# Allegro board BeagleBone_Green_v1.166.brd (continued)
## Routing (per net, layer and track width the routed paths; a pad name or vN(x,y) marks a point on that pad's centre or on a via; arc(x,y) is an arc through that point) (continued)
DDR_DQS0: length 23.3
  TOP w0.095: U5.P1 54.02,98.04 55.15,98.04 56.02,98.91 64.39,98.91 64.52,98.78 64.52,98.56 64.39,98.43 63.4,98.43 63.09,98.11 63.09,97.4 64.62,95.87 64.62,91.66 64.33,91.37 64.15,91.37 64.07,91.45 64.07,91.85 64,91.93 63.77,91.93 63.69,91.85 63.69,91.57 63.61,91.49 63.02,91.49 62.94,91.57 62.94,91.81 63.02,91.89 U12.F3
DDR_DQS1: length 20.3
  TOP w0.095: v1(55.24,95.94) 54.84,95.54 U5.L1
  TOP w0.121: v1(66.9,94.69) U12.C7
  BOTTOM w0.095: v1(55.24,95.94) 55.02,96.16 55.02,96.37 55.14,96.49 55.87,96.49 56.16,96.79 56.16,97.17 55.78,97.55 55.78,97.78 56.15,98.15 64.26,98.15 65.53,96.88 65.53,96.49 65.3,96.27 65.04,96.27 64.74,95.98 64.74,95.39 65.04,95.1 66.94,95.1 67.01,95.02 67.01,94.77 66.94,94.69 v1(66.9,94.69)
DDR_DQSN0: length 23.3
  TOP w0.095: U12.G3 64.45,91.09 64.9,91.54 64.9,95.99 63.37,97.52 63.37,98 63.52,98.15 64.5,98.15 64.8,98.44 64.8,98.9 64.5,99.19 55.91,99.19 55.04,98.32 53.5,98.32 U5.P2
DDR_DQSN1: length 20.3
  TOP w0.095: v1(54.48,95.94) 53.52,95.94 U5.L2
  TOP w0.121: v1(66.9,95.49) U12.B7
  BOTTOM w0.095: v1(66.9,95.49) 66.78,95.38 65.15,95.38 65.02,95.5 65.02,95.86 65.15,95.99 65.42,95.99 65.81,96.38 65.81,96.99 64.37,98.43 56.04,98.43 55.5,97.89 55.5,97.43 55.88,97.05 55.88,96.9 55.75,96.77 55.03,96.77 54.74,96.48 54.74,96.19 v1(54.48,95.94)
DDR_ODT: length 24.1
  TOP w0.121: U5.G1 55.08,92.34 55.72,92.34 56.52,91.54 56.52,90.65 56.9,90.27 57.53,90.27 57.78,90.02 57.78,86.82 57.89,86.72 58.04,86.72 58.15,86.82 58.15,89.38 58.26,89.49 58.69,89.49 58.8,89.38 58.8,88.75 58.95,88.6 58.95,87.22 59.07,87.1 59.31,87.1 59.44,87.22 59.44,88.87 v1(59.31,89) ; v1(61.3,88.29) U12.K1
  LYR3 w0.133: v1(61.3,88.29) 60.63,88.29 60.32,87.99 59.44,87.99 59.31,88.11 59.31,88.37 59.44,88.49 59.69,88.49 59.82,88.62 59.82,90.02 59.56,90.27 59.18,90.27 59.05,90.14 59.05,89.76 59.31,89.51 v1(59.31,89)
DDR_RASN: length 24
  TOP w0.121: v1(62.9,89.09) U12.J3 ; U5.G4 v1(51.92,91.94)
  LYR3 w0.121: 52.73,89.89 52.57,89.89 52.32,90.14 52.32,90.53 52.11,90.74 51.73,90.74 51.52,90.95 51.52,91.54 v1(51.92,91.94)
  LYR3 w0.133: 52.73,89.89 55.63,89.89 56.13,90.4 56.13,91.03 55.64,91.53 54.86,91.53 54.74,91.66 54.74,92.56 54.86,92.68 56.39,92.68 57.89,91.18 59.16,91.18 60.82,89.52 62.75,89.52 62.99,89.76 63.5,89.76 64.24,89.03 64.24,88.85 64.09,88.7 63.91,88.7 63.52,89.09 v1(62.9,89.09)
DDR_RESETN: length 20.7
  TOP w0.121: U5.G2 53.52,92.74 55.83,92.74 56.9,91.67 56.9,90.91 57.15,90.65 57.78,90.65 58.15,90.29 59.29,90.29 59.82,89.76 59.82,87.1 60.07,86.84 60.07,83.16 60.2,83.03 61.64,83.03 v1(62.1,83.49) U12.T2
  BOTTOM w0.121: v1(62.1,83.49) U12.T2 63.35,83.89 63.75,84.29 R97.2
DDR_VREF: length 27.1
  TOP w0.305: v1(51.92,93.54) U5.J4 ; v1(61.3,90.69) U12.H1 ; v1(67.7,86.69) U12.M8
  BOTTOM w0.381: v1(67.7,86.69) 66.57,86.69 66.17,87.09 C124.1 R100.1 65.41,88.51 65.02,88.89 64.86,88.89 64.85,88.89 64.62,88.89 64.39,89.13 C123.1 R98.2 ; v1(51.92,93.54) 52.46,94.08 55.88,94.08 56.43,93.54 C28.1 56.77,92.56 57.71,91.62 60.76,91.62 60.87,91.73 61.73,91.73 61.74,91.72 63.91,91.72 64.39,91.24 R98.2 ; R98.2 63.79,90.69 63.22,90.12 61.87,90.12 v1(61.3,90.69)
DDR_VTP: length 6.7
  TOP w0.305: v1(52.72,93.54) U5.J3
  BOTTOM w0.381: R22.2 56.26,91.29 56.26,92.81 55.54,93.54 v1(52.72,93.54)
DDR_WEN: length 23.9
  TOP w0.121: v1(62.9,87.49) U12.L3 ; v1(56.77,82.65) 56.77,82.8 54.86,84.71 54.86,85.45 54.36,85.95 53.64,85.95 53.51,86.08 53.51,87.7 53.12,88.1 U5.B2
  LYR3 w0.133: v1(56.77,82.65) 56.78,82.65 57.03,82.65 58.17,81.51 63.63,81.51 64.52,82.4 64.52,85.7 64.9,86.08 64.9,86.84 63.88,87.86 63.27,87.86 v1(62.9,87.49)
EHRPWM1A: length 42.1
  TOP w0.121: v1(41.73,103.43) 42.42,104.11 43.03,104.11 43.92,103.23 43.92,100.74 U5.U14
  LYR4 w0.133: P9.14 36.3,69.6 36.3,74.24 36.96,74.9 36.96,84.05 36.82,84.18 36.82,88.24 36.95,88.37 36.95,90.91 37.46,91.41 37.46,92.19 38.63,93.37 38.63,98.68 41.73,101.78 v1(41.73,103.43)
EHRPWM1B: length 36.3
  TOP w0.121: v1(43.12,99.94) U5.T14
  LYR4 w0.133: v1(43.12,99.94) 43.12,100.49 42.48,101.12 42.04,101.12 39.37,98.45 39.37,92.3 37.69,90.63 37.69,88.01 37.88,87.82 37.88,84.52 38.35,84.05 38.35,70.08 P9.16
EHRPWM2A: length 16.8
  TOP w0.121: P8.19 45.97,113.26 45.97,110.59 47.57,108.99 47.57,101.75 47.36,101.53 47.35,101.53 47.12,101.3 47.12,101.2 47.12,101.19 47.12,100.74 U5.U10
EHRPWM2B: length 28.2
  TOP w0.121: v1(46.32,99.94) U5.T10
  LYR3 w0.133: P8.13 34.9,113.87 34.9,108.8 35.85,107.85 38.66,107.85 40,109.19 43.69,109.19 44.7,108.18 44.7,106.78 44.1,106.18 44.1,105.67 44.98,104.78 44.98,104.47 45.78,103.68 45.78,100.48 v1(46.32,99.94)
EMMC_RSTN: length 4.8
  TOP w0.203: U13.K5 v1(30.49,108.79)
  BOTTOM w0.121: R162.2 R111.2 30.61,109.69 30.49,109.58 v1(30.49,108.79)
EMMC_VCCI: length 2.5
  TOP w0.076: 33.27,110.47 33.24,110.45 33.24,110.03 U13.C2
  TOP w0.121: 33.27,110.47 33.74,110.95 v1(34.01,110.95)
  BOTTOM w0.121: v1(34.01,110.95) 34.01,111.02 33.78,111.25 C125.1
ENZ_KALDO_1P8V: length 3.4
  TOP w0.121: U5.B4 v1(51.92,87.93)
  BOTTOM w0.121: v1(51.92,87.93) 52.51,87.34 R54.2
ETH_TXD4: length 4.4
  TOP w0.121: v1(30.61,99.73) 28.13,99.73 27.73,99.33 U14.18
  BOTTOM w0.121: R145.1 v1(30.61,99.73)
GPIO0_7: length 45.9
  TOP w0.121: R50.1 37.72,83.41 v1(37.46,83.16)
  BOTTOM w0.121: P9.42 70.29,71.16 68.85,71.16 61.29,78.71 48.39,78.71 48.2,78.53 44.15,78.53 42.67,80.01 42.67,83.03 42.04,83.67 R51.1 41.15,84.3 40.77,84.68 39.24,84.68 38.61,85.32 38.1,85.32 37.86,85.08 37.86,84.58 37.46,84.18 v1(37.46,83.16)
GPIO0_7SRC: length 9.2
  TOP w0.121: R50.2 37.46,82.4 37.01,82.85 37.01,85.12 38.48,86.59 38.48,87.6 40.01,89.14 U5.C18
GPIO0_26: length 30.5
  TOP w0.121: v1(45.52,99.94) U5.T11
  LYR3 w0.133: v1(45.52,99.94) 45.52,103.56 44.63,104.44 44.63,104.81 43.81,105.63 43.81,106.39 44.45,107.04 44.45,108.05 43.69,108.81 39.96,108.81 38.76,107.61 35.75,107.61 34.66,108.7 34.66,108.9 34.66,114.82 35.05,115.21 35.05,116.56 P8.14
GPIO0_27: length 18.3
  TOP w0.121: P8.17 41.4,114.91 41.86,114.45 42.93,114.45 43.23,114.15 44.07,114.15 44.7,113.51 44.7,110.5 45.59,109.61 45.59,105.51 45.12,105.04 45.12,102.24 45.51,101.84 45.51,100.73 U5.U12
GPIO1_12: length 30.2
  TOP w0.121: v1(44.72,99.94) U5.T12
  LYR3 w0.133: v1(44.72,99.94) 44.72,103.26 43.89,104.09 43.89,104.88 43.28,105.49 43.28,107.57 42.55,108.31 40.29,108.31 39.12,107.13 35.55,107.13 35.37,106.95 34.84,106.95 33.66,108.14 33.66,108.84 32.83,109.67 32.83,116.87 P8.12
GPIO1_13: length 28.5
  TOP w0.121: v1(44.72,99.14) U5.R12
  LYR3 w0.121: 45.16,103.4 45.16,100.15 45.12,100.1 45.12,99.77 45.16,99.73 45.16,99.58 v1(44.72,99.14)
  LYR3 w0.133: P8.11 33.38,114.88 33.38,109.63 34.09,108.92 34.09,108.04 34.93,107.19 35.27,107.19 35.45,107.37 38.94,107.37 40.13,108.56 42.67,108.56 43.56,107.67 43.56,105.54 44.37,104.73 44.37,104.19 45.16,103.4
GPIO1_14: length 22.1
  TOP w0.121: P8.16 37.85,116.81 37.85,114.6 39.19,113.26 42.42,113.26 43.18,112.5 43.18,110.46 44.45,109.19 44.45,107.04 43.94,106.53 43.94,104.11 44.32,103.74 44.32,101.48 U5.V13
GPIO1_15: length 19.9
  TOP w0.121: U5.U13 44.72,100.74 44.72,100.9 44.72,101.69 44.58,101.83 44.58,103.86 44.2,104.24 44.2,106.27 44.83,106.91 44.83,109.32 43.43,110.72 43.43,112.75 42.55,113.63 39.43,113.63 38.86,114.2 P8.15
GPIO1_16: length 55
  LYR4 w0.133: v1(43.69,108.18) 43.43,108.43 40.64,108.43 37.59,105.38 37.59,104.88 34.92,102.21 34.92,89.2 32.64,86.92 32.64,84.58 33.15,84.07 33.15,72.49 32.64,71.98 32.64,69.19 33.66,68.17 37.72,68.17 P9.15
  BOTTOM w0.133: v1(43.69,108.18) 43.81,108.05 R160.2 R161.2
GPIO1_17: length 53.4
  TOP w0.121: v1(42.8,103.71) 42.85,103.71 43.52,103.04 U5.V14
  LYR4 w0.133: v1(42.8,103.71) 42.76,103.71 42.09,103.04 42.09,101.68 39.1,98.69 39.1,93.5 37.69,92.1 37.69,91.29 37.21,90.8 37.21,88.24 37.06,88.09 37.06,84.43 37.87,83.62 37.87,75.11 36.7,73.94 v1(36.7,71.6)
  BOTTOM w0.121: P9.23 47.75,68.3 47.75,69.95 46.99,70.71 37.59,70.71 v1(36.7,71.6)
GPIO1_28: length 38.6
  TOP w0.121: v1(38.4,102.46) 38.41,102.46 38.97,101.9 38.97,101.46 39.16,101.27 39.16,101.23 40.05,100.34 U5.U18
  LYR4 w0.133: v1(38.4,102.46) 38.35,102.46 37.92,102.03 37.92,101.75 37.71,101.54 36.54,101.54 35.69,100.69 35.69,88.62 35.43,88.37 35.43,82.91 34.06,81.53 34.06,70.99 33.78,70.71 P9.12
GPIO1_29: length 18
  TOP w0.121: P8.26 50.55,116.81 50.55,114.53 50.8,114.27 50.8,110.21 49.4,108.81 49.4,104.37 49.92,103.85 U5.V6
GPIO2_1: length 20.3
  TOP w0.121: P8.18 40.41,116.84 40.41,114.81 41.15,114.07 42.62,114.07 44.45,112.24 44.45,110.21 45.34,109.32 45.34,105.64 44.83,105.13 44.83,102.08 45.12,101.8 U5.V12
GPIO3_18: length 5.9
  TOP w0.121: v1(41.4,85.32) 42.16,85.32 43.49,86.64 44,86.64 44.71,87.36 44.71,87.93 U5.B12
  BOTTOM w0.121: v1(41.4,85.32) R51.2
GPIO3_19: length 28.2
  TOP w0.121: v1(43.92,88.73) U5.C13
  LYR4 w0.133: v1(43.92,88.73) 43.25,88.07 43.25,86.8 43.78,86.27 43.78,82.49 44.32,81.94 44.32,79.12 46.58,76.86 46.58,75.51 47.88,74.22 47.88,72.34 50.16,70.05 50.16,68.94 50.93,68.17 52.96,68.17 P9.27
GPIO3_20: length 5.9
  TOP w0.121: U5.D13 v1(43.92,90.34)
  BOTTOM w0.121: v1(43.92,90.34) 43.52,89.94 43.52,86.51 43.94,86.08 R20.2
GPIO3_21: length 58.4
  TOP w0.121: v1(39.95,106.53) 39.75,106.53 39.37,106.91 ; U5.A14 43.52,87.34 42.13,85.95 41.15,85.95 v1(40.51,85.32) 40.39,85.19 40.39,81.76 41.78,80.37 41.78,76.35 42.65,75.49 42.65,72.01 43.18,71.48 45.59,71.48 46.33,70.74 49.63,70.74 50.29,70.08 50.29,68.3 P9.25
  LYR3 w0.133: v1(40.51,85.32) 40.13,85.32 39.37,86.08 37.08,86.08 36.45,86.72 v1(36.45,88.67)
  LYR4 w0.133: v1(36.45,88.67) 36.45,99.29 36.7,99.54 38.73,99.54 40.13,100.94 40.13,101.45 39.88,101.7 39.88,106.46 v1(39.95,106.53)
GRN_C: length 2
  BOTTOM w0.381: P5.10 6.27,97.71 6.6,97.38 R132.2
GRNA: length 30
  TOP w0.121: 25.73,92.93 v1(25.84,92.81)
  TOP w0.254: U14.3 25.73,92.93
  BOTTOM w0.254: v1(25.84,92.81) 25.59,93.07 25.02,93.07 24.77,92.82 24.77,92.69 24.51,92.43 22.35,92.43 19.18,89.26 16.51,89.26 13.59,92.18 12.19,92.18 11.56,92.81 11.56,93.19 9.02,95.73 C165.1 C163.1 9.02,97 7.49,98.53 7.49,98.84 7.23,99.24 6.16,100.3 5.74,100.3 P5.9
HDMI_INT: length 22.1
  TOP w0.121: U5.U16 41.52,100.73 41.52,101.96 41.1,102.39 39.09,102.39 38.51,102.97 37.78,102.97 37.76,102.99 37.43,102.99 37.41,102.97 36.22,102.97 35.94,102.69 27.28,102.69 26.14,103.84 R170.1 23.37,103.86 R169.1
HDMICLK_DISN: length 5.3
  TOP w0.121: v1(40.89,104.62) 40.89,104.75 41.14,105 41.16,105 41.74,105.58 Y4.1 ; U5.V17 41.12,101.76 v1(41.05,101.83)
  LYR3 w0.133: v1(40.89,104.62) 40.89,101.98 v1(41.05,101.83)
I2C0_SCL: length 27.9
  TOP w0.121: R3.2 27.43,85.57 v1(28.32,84.68) ; v1(28.32,79.16) 28.11,79.37 U2.28 ; v1(41.52,88.73) U5.C16
  LYR4 w0.133: v1(28.32,84.68) 28.96,84.05 28.96,79.79 v1(28.32,79.16)
  BOTTOM w0.121: v1(28.32,84.68) 29.59,84.68 30.38,85.47 30.38,86.87 31.5,87.99 U7.1 33.12,87.99 33.38,87.73 37.57,87.73 39.07,86.23 40.53,86.23 41.12,86.81 41.12,88.34 v1(41.52,88.73)
I2C0_SDA: length 33.2
  TOP w0.121: U2.27 27.88,78.97 v1(28.32,78.52) ; U5.C17 40.72,88.74 40.12,88.74 38.73,87.35 38.73,86.54 38.73,86.53 38.73,86.49 37.46,85.22 v1(37.46,84.81) ; R4.2 v1(28.38,85.7)
  LYR3 w0.133: v1(37.46,84.81) 36.2,84.81 34.67,86.33 29.02,86.33 v1(28.38,85.7)
  LYR4 w0.133: v1(28.32,78.52) 29.21,79.41 29.21,84.87 v1(28.38,85.7)
  BOTTOM w0.121: v1(28.38,85.7) 27.81,85.13 27.81,84.43 28.07,84.18 29.72,84.18 30.73,85.19 31.88,85.19 32.22,85.53 U7.3
I2C1_SCL: length 25.2
  TOP w0.121: U5.A16 v1(41.52,87.13)
  TOP w0.133: P9.17 42.55,68.17 42.55,70.71 41.4,71.86 v1(41.4,72.11)
  LYR4 w0.133: v1(41.4,72.11) 44.7,75.41 44.87,75.41 45.65,76.19 45.65,76.8 43.27,79.18 43.27,79.98 42.63,80.62 42.63,85.87 41.52,86.98 v1(41.52,87.13)
I2C1_SDA: length 23.1
  TOP w0.121: U5.B16 v1(41.52,87.93)
  LYR4 w0.133: P9.18 41,69.98 41,72.28 44.38,75.67 44.8,75.67 45.41,76.29 45.41,76.7 43.03,79.08 43.03,79.88 42.39,80.52 42.39,85.67 41.11,86.95 41.11,87.53 v1(41.52,87.93)
I2C2_SCL: length 73.5
  TOP w0.121: U5.D17 40.72,89.54 39.9,89.54 38.86,88.49 v1(38.1,88.49) ; J4.1 v1(75.77,86.67)
  LYR3 w0.133: v1(41.12,78.71) 45.82,78.71 49,75.54 54.71,75.54 57.66,78.49 69.69,78.49 75.18,83.98 75.18,86.08 v1(75.77,86.67)
  LYR4 w0.133: P9.19 42.8,68.17 40.82,68.17 40.02,68.97 40.02,77.62 v1(41.12,78.71) 38.86,80.98 38.86,85.47 38.5,85.83 38.5,88.09 v1(38.1,88.49)
I2C2_SDA: length 71.1
  TOP w0.121: U5.D18 39.8,89.94 38.86,89 38.23,89 v1(38.1,89.13) ; J4.2 v1(75.69,84.67)
  LYR3 w0.133: v1(41.27,77.95) 41.53,78.21 45.92,78.21 48.83,75.3 54.88,75.3 57.78,78.21 69.74,78.21 75.69,84.16 v1(75.69,84.67)
  LYR4 w0.133: v1(38.1,89.13) 38.73,88.49 38.73,86.06 39.14,85.65 39.14,81.14 41.06,79.22 41.19,79.22 41.55,78.86 41.55,78.22 v1(41.27,77.95) 40.26,76.94 40.26,69.06 40.77,68.55 42.93,68.55 P9.20
JTAG_EMU0: length 23.6
  TOP w0.121: R23.2 37.45,77 35.69,78.77 v1(35.69,80.05) ; v1(43.12,88.73) U5.C14
  LYR3 w0.133: v1(35.69,80.05) 36.26,80.62 39.75,80.62 40,80.87 v1(43.81,80.87)
  LYR4 w0.133: v1(43.12,88.73) 43.12,88.36 42.99,88.24 42.99,86.68 43.36,86.31 43.36,86.24 43.37,86.22 43.37,81.32 v1(43.81,80.87)
  BOTTOM w0.121: P2.13 v1(35.69,80.05)
JTAG_EMU1: length 15.3
  TOP w0.121: R24.2 37.66,80.24 v1(37.46,80.05) ; v1(41.12,80.37) 41.05,80.37 39.99,81.43 39.99,85.43 40.89,86.33 42.16,86.33 43.12,87.29 43.12,87.94 U5.B14
  BOTTOM w0.121: v1(41.12,80.37) 40.89,80.37 40.58,80.05 P2.14 v1(37.46,80.05)
JTAG_TCK: length 24.1
  TOP w0.121: v1(42.55,77.06) 42.29,77.32 42.29,80.49 41.78,81 41.78,84.43 43.75,86.39 44.13,86.39 44.8,87.07 44.8,87.07 45.12,87.38 U5.A12
  LYR3 w0.133: v1(35.69,77.51) 42.1,77.51 v1(42.55,77.06)
  BOTTOM w0.121: P2.11 35.5,78.78 35.69,78.59 v1(35.69,77.51) P2.9
JTAG_TDI: length 24.1
  TOP w0.121: v1(43.19,77.03) 42.67,77.55 42.67,80.71 42.2,81.19 42.2,84.34 43.91,86.05 44.27,86.05 45.52,87.29 45.52,87.94 U5.B11
  BOTTOM w0.121: v1(43.19,77.03) 42.81,76.65 41.9,76.65 40.86,75.6 37.66,75.6 35.75,73.7 P2.3
JTAG_TDO: length 23.7
  TOP w0.121: v1(43.23,76.35) 43.71,76.84 43.71,77.32 43.05,77.98 43.05,80.94 42.55,81.44 42.55,84.18 43.94,85.57 43.94,85.57 44.96,85.57 45.59,86.21 45.59,86.84 45.92,87.17 U5.A11
  LYR3 w0.133: v1(35.69,76.24) 36.44,76.99 41.58,76.99 42.21,76.35 v1(43.23,76.35)
  BOTTOM w0.121: P2.7 v1(35.69,76.24)
JTAG_TMS: length 28.8
  TOP w0.121: v1(45.59,74.02) 46.04,74.46 46.04,80.43 v1(46.48,80.87) ; U5.C11 v1(45.52,88.73)
  LYR4 w0.133: v1(46.48,80.87) 45.78,81.57 45.78,86.73 45.52,87 v1(45.52,88.73)
  BOTTOM w0.121: P2.1 36.26,72.43 36.89,73.06 41.59,73.06 43.05,74.52 45.09,74.52 v1(45.59,74.02)
JTAG_TRSTN: length 25.6
  TOP w0.121: R25.1 38.23,72.62 38.04,72.43 v1(37.46,72.43) ; v1(43.94,74.02) 43.97,74.04 43.97,77.55 43.31,78.21 43.31,81.13 42.8,81.64 42.8,84.05 44.07,85.32 45.09,85.32 45.85,86.08 45.85,86.72 46.32,87.19 46.32,87.94 U5.B10
  BOTTOM w0.121: v1(37.46,72.43) P2.2 40.32,72.43 40.51,72.62 41.66,72.62 43.05,74.02 v1(43.94,74.02)
LCD_DATA0: length 33.1
  TOP w0.121: R95.1 v1(77.34,113.39) ; U5.R1 54.03,98.74 55.32,100.03 58.65,100.03 v1(59.28,100.66)
  LYR3 w0.133: v1(77.34,113.39) 75.82,111.86 75.31,111.86 72.11,108.66 71.66,108.66 68.23,105.23 63.85,105.23 v1(59.28,100.66)
  BOTTOM w0.121: P8.45 76.96,113.77 v1(77.34,113.39) R95.1
LCD_DATA1: length 35.7
  TOP w0.121: R94.1 v1(75.57,113.51) ; v1(58.55,100.69) 56.77,100.69 56.46,100.38 55.32,100.38 54.31,99.37 54.31,99.37 54.08,99.14 54.08,99.14 53.5,99.14 53.12,98.75 U5.R2
  LYR3 w0.133: v1(75.57,113.51) 75.57,112.68 72.81,109.92 72.59,109.92 68.32,105.65 63.51,105.65 v1(58.55,100.69)
  BOTTOM w0.121: R94.1 v1(75.57,113.51) 75.57,116.43 P8.46
LCD_DATA2: length 37
  TOP w0.121: R93.1 v1(74.68,113.51) ; v1(74.68,113.51) 74.93,113.51 75.44,114.02 77.47,114.02 78.23,113.26 R75.1 ; v1(74.68,113.51) 74.42,113.77 P8.43 ; v1(52.72,99.14) U5.R3
  LYR3 w0.133: v1(52.72,99.14) 52.83,99.14 52.98,99.28 52.99,99.28 53.84,100.13 57.35,100.13 63.25,106.02 67.51,106.02 72.59,111.11 72.59,111.43 v1(74.68,113.51)
  BOTTOM w0.121: R93.1 v1(74.68,113.51)
LCD_DATA3: length 35.6
  TOP w0.121: P8.44 73.33,116.74 73.33,114.29 73.79,113.83 v1(73.79,113.51) R92.1 ; v1(51.92,99.14) U5.R4
  LYR3 w0.133: v1(73.79,113.51) 71.95,111.67 71.95,110.79 67.43,106.27 63.17,106.27 57.3,100.41 53.75,100.41 52.88,99.54 52.32,99.54 v1(51.92,99.14)
  BOTTOM w0.121: R92.1 v1(73.79,113.51)
LCD_DATA4: length 28.1
  TOP w0.121: v1(56.16,100.84) 55.37,100.84 54.07,99.54 U5.T1
  LYR3 w0.133: v1(70.48,109.91) 67.23,106.65 63.12,106.65 57.3,100.84 v1(56.16,100.84)
  BOTTOM w0.121: P8.41 69.77,113.18 R66.2 69.72,112.62 69.29,112.19 69.29,110.64 69.72,110.21 R91.1 70.18,110.21 v1(70.48,109.91)
LCD_DATA5: length 31.1
  TOP w0.121: U5.T2 53.51,99.93 54.09,99.93 55.7,101.55 v1(56.16,101.55)
  LYR3 w0.133: v1(56.16,101.55) 57.63,101.55 62.99,106.91 66.72,106.91 68.61,108.8 68.61,109.21 69.15,109.75 v1(69.19,109.75)
  BOTTOM w0.121: v1(69.19,109.75) 68.99,109.96 68.71,109.96 68.58,110.08 R90.1 69.04,110.67 69.04,112.17 R65.2 68.58,113.51 69.22,114.15 69.72,114.15 70.61,115.04 70.61,116.56 P8.42
LCD_DATA6: length 27.3
  TOP w0.121: v1(52.68,99.95) 52.68,99.9 U5.T3
  LYR3 w0.133: v1(52.68,99.95) 53.59,100.86 54.91,100.86 55.75,101.7 55.75,101.72 55.99,101.96 57.66,101.96 62.99,107.29 65.85,107.29 67.46,108.9 67.46,110.8 v1(67.39,110.87)
  BOTTOM w0.121: R89.1 67.69,110.57 v1(67.39,110.87) 67.18,111.07 67.18,112.12 R64.2 67.69,113.64 P8.39
LCD_DATA7: length 30.3
  TOP w0.121: v1(51.92,99.94) U5.T4
  LYR3 w0.133: v1(67.06,109.78) 65.94,108.66 65.94,107.95 65.53,107.54 62.87,107.54 57.59,102.27 55.94,102.27 54.86,101.19 53.17,101.19 v1(51.92,99.94)
  BOTTOM w0.121: P8.40 67.95,116.43 67.95,114.91 66.42,113.39 R63.2 66.55,112.62 66.93,112.24 66.93,111.07 66.42,110.57 R88.1 66.62,110.21 v1(67.06,109.78)
LCD_DATA8: length 23.7
  TOP w0.121: U5.U1 54.11,100.34 54.74,100.97 54.74,101.7 v1(54.99,101.96)
  LYR3 w0.133: v1(54.99,101.96) 55.29,101.96 55.88,102.54 57.48,102.54 62.74,107.8 64.77,107.8 65.02,108.05 65.02,109.28 65.33,109.59 65.33,110.8 v1(65.25,110.87)
  BOTTOM w0.121: R87.1 65.53,110.59 v1(65.25,110.87) 65.02,111.1 65.02,112.12 R62.2 65.53,114.02 P8.37
LCD_DATA9: length 26.9
  TOP w0.121: U5.U2 53.36,100.34 53.75,100.73 54.12,100.73 54.48,101.09 54.48,102.08 v1(54.99,102.59)
  LYR3 w0.133: v1(54.99,102.59) 55.37,102.59 55.63,102.84 57.4,102.84 62,107.44 62,108.52 62.71,109.23 64.4,109.23 v1(64.92,109.75)
  BOTTOM w0.121: P8.38 65.66,116.69 65.66,114.63 64.26,113.23 R61.2 64.77,112.12 64.77,110.72 R86.1 64.72,109.75 v1(64.92,109.75)
LCD_DATA10: length 26.5
  TOP w0.121: v1(53.62,102.64) 53.51,102.54 53.51,100.97 53.28,100.74 52.72,100.74 U5.U3
  LYR3 w0.133: v1(53.62,102.64) 54.09,103.11 57.29,103.11 61.72,107.54 61.72,109.45 v1(63.14,110.87)
  BOTTOM w0.121: P8.36 65.28,116.81 65.28,114.78 63.37,112.88 R60.2 62.87,112.12 62.87,111.15 v1(63.14,110.87) 63.37,110.64 R85.1
LCD_DATA11: length 25
  TOP w0.121: v1(52.58,102.34) 51.92,101.68 51.92,100.74 U5.U4 ; v1(57.66,113.51) R84.1
  LYR3 w0.133: v1(57.66,113.51) 57.02,112.88 55.63,112.88 53.26,110.52 53.26,104.09 52.81,103.63 52.81,102.57 v1(52.58,102.34)
  BOTTOM w0.121: R84.1 v1(57.66,113.51) 58.17,114.02 58.17,115.93 58.67,116.43 60.07,116.43 61.47,117.83 P8.34
LCD_DATA12: length 24.3
  TOP w0.121: U5.V2 53.12,102.85 v1(53.59,103.33)
  LYR3 w0.133: v1(53.59,103.33) 53.99,103.72 53.99,109.59 54.48,110.08 60.35,110.08 60.55,110.29 61.85,110.29 v1(62.48,110.92)
  BOTTOM w0.121: R83.1 62.1,110.54 v1(62.48,110.92) 62.61,111.05 62.61,112.12 R58.2 62.1,113.13 P8.35
LCD_DATA13: length 22.5
  TOP w0.121: U5.V3 52.32,101.36 v1(52.63,101.68)
  LYR3 w0.133: v1(60.78,110.9) 60.4,110.9 59.84,110.34 54.23,110.34 53.52,109.63 53.52,103.86 53.14,103.48 53.14,102.18 v1(52.63,101.68)
  BOTTOM w0.121: R82.1 61.21,110.46 v1(60.78,110.9) 60.71,110.97 60.71,112.12 R57.2 61.21,114.78 P8.33
LCD_DATA14: length 19.3
  TOP w0.121: P8.31 58.17,114.27 55.37,114.27 54.99,113.89 54.99,113.26 R56.2 53.98,112.24 53.98,110.34 54.36,109.96 R81.1 53.72,108.94 53.72,108.18 53.34,107.8 53.34,103.99 51.52,102.16 U5.V4
LCD_DATA15: length 24.4
  TOP w0.121: R80.1 55.37,113.39 v1(55.63,113.64) ; v1(51.12,99.94) U5.T5
  LYR3 w0.133: v1(55.63,113.64) 55.63,113.21 53.03,110.61 53.03,109.26 52.2,108.43 52.2,102.97 51.12,101.89 v1(51.12,99.94)
  BOTTOM w0.121: R55.2 v1(55.63,113.64) 56.26,114.27 57.4,114.27 57.91,114.78 57.91,116.69 59.05,117.83 P8.32
LCD_DE: length 15.3
  TOP w0.121: R48.2 51.56,107.42 52.2,108.05 52.2,109.83 51.82,110.21 51.82,112.5 52.96,113.64 52.96,115.93 53.47,116.43 55.24,116.43 56.64,117.83
LCD_HSYNC: length 11.5
  TOP w0.121: 56.64,115.29 55.5,115.29 53.54,113.33 53.54,111.17 53.47,111.1 53.47,108.31 52.83,107.67 R47.2
LCD_PCLK: length 9.3
  TOP w0.121: R45.2 51.56,112.78 52.58,113.79 52.58,116.31 P8.28
LCD_VSYNC: length 6.6
  TOP w0.121: R46.2 52.83,110.72 52.45,111.1 52.45,112.62 54.1,114.27 P8.27
LCDDE: length 6.9
  TOP w0.121: v1(50.32,99.14) U5.R6 ; R48.1 v1(51.56,104.24)
  LYR3 w0.121: 50.72,100.3 50.72,99.54 v1(50.32,99.14)
  LYR3 w0.133: v1(51.56,104.24) 50.8,103.48 50.8,102.84 50.72,102.76 50.72,100.3
LCDPCLK: length 7.8
  TOP w0.121: U5.V5 50.72,102.34 51.05,102.67 51.05,107.42 51.56,107.92 R45.1
LCDVHYNC: length 7.1
  TOP w0.121: v1(51.12,99.14) U5.R5 ; v1(52.83,104.24) R47.1
  LYR3 w0.121: 51.52,100.26 51.52,99.54 v1(51.12,99.14)
  LYR3 w0.133: v1(52.83,104.24) 52.48,103.89 52.48,102.87 51.52,101.91 51.52,100.26
LCDVSYNC: length 9.1
  TOP w0.121: U5.U5 51.12,100.74 51.12,102.15 52.11,103.14 52.11,107.33 52.83,108.05 R46.1
LDO_PGOOD: length 35.6
  TOP w0.121: v1(22.22,84.75) 22.86,84.12 U2.46 ; U5.B5 v1(51.12,87.93)
  LYR3 w0.133: v1(51.12,87.93) 51.12,85.64 50.8,85.32 48.74,85.32 47.75,84.33 39.57,84.33 38.68,85.22 36.3,85.22 34.92,86.59 28.45,86.59 27.3,85.45 22.92,85.45 v1(22.22,84.75)
LEDAA: length 6.3
  TOP w0.381: D2.2 7.87,114.15 8.25,113.77 8.25,113.39 8.76,112.88 12.57,112.88 R72.2
LEDAC: length 17.4
  TOP w0.121: Q1.6 20.69,110.48 20.45,110.72 v1(19.94,110.72) ; v1(7.62,113.26) 6.1,113.26 5.52,113.83 D2.1
  LYR3 w0.133: v1(7.62,113.26) 8.25,112.62 18.03,112.62 v1(19.94,110.72)
LEDBA: length 5.7
  TOP w0.381: D3.2 7.68,111.86 R73.2
LEDBC: length 22.1
  TOP w0.121: D3.1 5.52,112.56 v1(4.7,113.39) ; v1(22.61,108.94) 22.22,108.94 21.99,108.7 Q1.3
  LYR3 w0.133: v1(4.7,113.39) 5.84,112.24 16.51,112.24 19.81,108.94 v1(22.61,108.94)
LEDCA: length 5.9
  TOP w0.381: R74.2 9.02,110.97 8.13,110.08 D4.2
LEDCC: length 13.8
  TOP w0.121: v1(6.73,111.35) 5.52,110.15 D4.1 ; Q2.6 18.02,110.23 17.91,110.34 17.4,110.34 v1(17.02,110.72)
  LYR3 w0.133: v1(6.73,111.35) 16.38,111.35 v1(17.02,110.72)
LEDDA: length 6.4
  TOP w0.381: R71.2 12.57,110.21 9.27,110.21 7.37,108.31 D5.2
LEDDC: length 19.1
  TOP w0.121: v1(19.94,107.59) 19.86,107.59 19.32,108.14 Q2.3 ; D5.1 5.46,108.31 v1(4.7,109.07)
  LYR3 w0.133: v1(19.94,107.59) 17.3,110.24 5.87,110.24 v1(4.7,109.07)
MDIO_CLK: length 14.5
  TOP w0.121: U14.17 28.23,99.3 28.35,99.42 30.1,99.42 30.23,99.29 33.4,99.29 33.91,99.8 34.8,99.8 36.7,97.89 37.08,97.89 38.1,96.88 39.12,96.88 39.75,96.24 40.22,96.24 U5.M18
MDIO_DATA: length 15
  TOP w0.121: U14.16 29.44,97.99 29.72,98.27 30.23,98.27 30.73,98.78 R119.2 31.85,98.3 33.37,98.3 33.66,98.59 33.66,99.03 34.05,99.43 34.78,99.43 36.58,97.64 36.96,97.64 37.97,96.62 38.99,96.62 39.67,95.94 40.72,95.94 U5.M17
MII1_COL: length 24.2
  TOP w0.121: v1(41.52,92.74) U5.H16
  LYR3 w0.133: v1(33.15,91.16) 32.51,91.16 32.38,91.03 32.38,90.4 32.26,90.27 31.24,90.27 31.11,90.4 31.11,91.54 31.24,91.67 33.78,91.67 33.91,91.8 33.91,92.94 34.04,93.07 41.19,93.07 v1(41.52,92.74)
  BOTTOM w0.121: R138.1 32.83,97.38 33.24,97.38 33.55,97.08 33.55,95.97 33.91,95.61 33.91,91.92 v1(33.15,91.16)
MII1_CRS_DV: length 25.6
  TOP w0.121: U5.H17 40.72,93.54 v1(38.23,93.54) ; R139.1 v1(33.15,97.83)
  BOTTOM w0.121: v1(38.23,93.54) 37.83,93.14 37.83,89.61 37.73,89.51 37.57,89.51 37.46,89.61 37.46,95.22 37.21,95.48 34.36,95.48 34.26,95.58 34.26,95.69 34.36,95.8 36.35,95.8 36.45,95.9 36.45,96.01 36.35,96.11 33.9,96.11 33.79,96.22 33.79,98.17 33.69,98.27 33.25,98.27 33.15,98.17 v1(33.15,97.83)
MII1_REFCLK: length 18.5
  TOP w0.121: R124.1 33.08,92.05 v1(33.15,92.11) 33.21,92.18 33.4,92.18 33.5,92.08 33.5,91.7 33.6,91.61 33.73,91.61 33.86,91.74 33.86,91.87 34.08,92.09 34.7,92.09 34.82,91.97 34.82,91.24 34.72,91.14 33.99,91.14 33.91,91.07 33.91,90.86 33.99,90.78 34.72,90.78 34.8,90.7 34.8,90.47 34.72,90.4 33.99,90.4 33.91,90.32 33.91,90.09 33.99,90.02 35.1,90.02 35.18,90.09 35.18,90.37 35.28,90.47 35.57,90.47 35.7,90.6 35.7,90.77 35.61,90.86 35.31,90.86 35.18,90.98 35.18,91.21 35.26,91.29 36.37,91.29 36.45,91.36 36.45,91.59 36.37,91.67 35.26,91.67 35.18,91.74 35.18,91.97 35.26,92.05 36.37,92.05 36.48,92.15 36.48,92.33 36.37,92.43 35.31,92.43 35.18,92.56 R28.2
  BOTTOM w0.121: v1(33.15,92.11) 33.15,91.92 R140.1
MII1_RXCLK: length 23.8
  TOP w0.121: U5.L18 39.69,95.54 38.86,96.37 37.85,96.37 36.83,97.38 36.45,97.38 35.18,98.65 34.92,98.65 34.82,98.55 34.82,98.13 34.69,98 33.66,98 33.55,97.89 33.55,97.76 33.67,97.63 34.06,97.63 34.16,97.53 34.16,95.71 34.26,95.61 34.38,95.61 34.48,95.71 34.48,96.9 34.58,97 34.76,97 34.86,96.9 34.86,94.46 34.73,94.34 34.04,94.34 33.91,94.46 33.91,95.16 33.59,95.48 33.25,95.48 33.15,95.58 v1(33.15,95.92)
  BOTTOM w0.121: R131.1 32.38,92.43 32.51,92.56 33.27,92.56 33.66,92.94 33.66,95.42 v1(33.15,95.92)
MII1_RXD0: length 24.3
  TOP w0.121: R128.1 33.15,96.69 v1(33.15,96.88) ; v1(40.72,96.74) 41.52,96.74 U5.M16
  LYR3 w0.133: v1(33.15,96.88) 32.36,96.88 32.26,96.98 32.26,101.09 32.36,101.19 33.68,101.19 33.78,101.09 33.78,100.28 33.68,100.18 32.77,100.18 32.64,100.05 32.64,99.42 32.77,99.29 33.68,99.29 33.78,99.19 33.78,98.37 33.68,98.27 32.77,98.27 32.64,98.15 32.64,97.55 32.77,97.42 33.76,97.42 34.04,97.14 40.31,97.14 v1(40.72,96.74)
MII1_RXD1: length 24.6
  TOP w0.121: v1(33.15,94.97) 32.89,95.22 32.64,95.22 R127.1 ; U5.L15 v1(42.32,95.14)
  LYR3 w0.121: v1(42.32,95.14) 41.92,94.74 41.15,94.74
  LYR3 w0.133: v1(33.15,94.97) 32.89,95.22 32.36,95.22 31.5,96.09 31.5,97 31.37,97.13 31.14,97.13 31.01,97 31.01,95.83 32.38,94.46 33.27,94.46 33.55,94.74 33.55,95.25 34.29,95.99 34.29,96.27 34.39,96.37 34.57,96.37 34.67,96.27 34.67,95.83 34.77,95.73 34.95,95.73 35.05,95.83 35.05,96.27 35.15,96.37 35.33,96.37 35.43,96.27 35.43,95.83 35.53,95.73 35.71,95.73 35.81,95.83 35.81,96.27 35.92,96.37 36.09,96.37 36.2,96.27 36.2,95.83 36.3,95.73 36.47,95.73 36.55,95.81 36.55,96.27 36.65,96.37 37.59,96.37 37.72,96.24 37.72,95.63 37.82,95.53 38.51,95.53 38.63,95.66 38.63,96.11 38.73,96.21 39,96.21 40.47,94.74 41.15,94.74
MII1_RXD2: length 24.2
  TOP w0.121: R126.1 32.38,94.36 32.49,94.46 32.79,94.46 32.89,94.36 32.89,94.12 32.99,94.02 33.17,94.02 33.27,94.12 33.27,94.49 33.38,94.59 33.55,94.59 33.66,94.49 33.66,94.12 33.76,94.02 35.05,94.02 35.18,94.15 35.18,97.16 35.08,97.26 34.52,97.26 34.42,97.36 34.42,97.54 34.52,97.64 34.95,97.64 35.05,97.74 35.05,98.04 35.15,98.15 35.34,98.15 36.08,97.4 36.08,95.97 36.2,95.86 36.35,95.86 36.47,95.97 36.47,97.03 36.57,97.14 36.7,97.14 36.97,96.87 36.97,96.48 37.07,96.38 37.46,96.38 37.61,96.24 37.61,96.07 37.46,95.92 37.25,95.92 v1(37.24,95.94) ; U5.L16 v1(42.32,95.94)
  BOTTOM w0.121: v1(37.24,95.94) 37.35,96.05 37.62,96.05 37.74,95.93 37.74,94.79 37.87,94.67 38.4,94.67 38.61,94.46 40.51,94.46 40.77,94.72 40.77,94.95 41.35,95.54 42.17,95.54 42.32,95.68 v1(42.32,95.94)
MII1_RXD3: length 24.2
  TOP w0.121: R125.1 33.02,93.7 35.31,93.7 35.43,93.83 35.43,97.28 35.53,97.38 35.71,97.38 35.81,97.28 35.81,93.8 35.92,93.7 37.49,93.7 37.58,93.79 37.58,94.48 37.49,94.57 37.36,94.57 37.26,94.47 37.26,94.06 37.15,93.95 36.96,93.95 36.86,94.06 36.86,94.33 36.78,94.41 36.7,94.41 36.58,94.29 36.58,94.06 36.47,93.95 36.3,93.95 36.2,94.06 36.2,95.38 36.3,95.48 37.08,95.48 37.34,95.22 37.49,95.22 37.74,95.48 38,95.48 38.25,95.22 38.53,95.22 38.63,95.33 38.63,95.9 38.71,95.99 38.89,95.99 38.99,95.89 38.99,95.24 39.09,95.14 40.93,95.14 41.12,95.32 U5.L17
MII1_RXDV: length 25.6
  TOP w0.121: v1(24.05,100.91) 23.34,100.91 R129.1 ; U5.J17 v1(41.52,94.34)
  LYR3 w0.133: v1(24.05,100.91) 24.18,100.79 24.18,99.03 25.35,97.87 26.77,97.87 30.15,94.49 31.04,94.49 31.72,93.8 33.38,93.8 34.02,94.45 34.02,94.99 34.21,95.17 36.09,95.17 36.73,94.54 37.11,94.54 37.77,95.2 39.62,95.2 40.36,94.46 41.39,94.46 v1(41.52,94.34)
MII1_RXERR: length 24.5
  TOP w0.121: v1(34.43,94.77) 34.42,94.78 34.42,95.1 33.55,95.96 33.55,96.65 33.79,96.88 33.79,97.28 33.69,97.38 32.83,97.38 32.79,97.35 32.47,97.35 32.38,97.26 R133.1 ; U5.J15 v1(42.32,94.34)
  LYR3 w0.121: 41.26,93.94 41.92,93.94 v1(42.32,94.34)
  LYR3 w0.133: v1(34.43,94.77) 34.39,94.73 34.39,93.68 34.49,93.58 34.81,93.58 34.9,93.68 34.9,94.77 35.03,94.89 35.2,94.89 35.36,94.74 35.36,93.76 35.49,93.63 35.72,93.63 35.81,93.72 35.81,94.72 35.92,94.82 36.1,94.82 36.22,94.7 36.22,93.73 36.36,93.6 36.58,93.6 36.68,93.7 36.68,94.13 36.78,94.23 36.97,94.23 37.06,94.14 37.06,93.67 37.13,93.6 37.41,93.6 37.54,93.73 37.54,94.49 37.95,94.89 38.61,94.89 38.99,94.51 38.99,93.75 39.16,93.58 39.35,93.58 39.45,93.68 39.45,94.62 39.52,94.69 39.73,94.69 39.85,94.56 39.85,93.7 39.95,93.61 40.22,93.61 40.31,93.7 40.31,94.01 40.41,94.11 40.7,94.11 40.87,93.94 41.26,93.94
MII1_TXCLK: length 22.8
  TOP w0.121: v1(36.95,95.05) 37.03,95.05 37.13,94.95 38.65,94.95 38.86,94.74 U5.K18
  LYR3 w0.133: v1(36.95,95.05) 36.54,95.45 34.11,95.45 33.79,95.13 33.79,94.62 33.27,94.11 32.23,94.11 30.89,95.45 29.74,95.45 29.13,96.06 29.13,96.47 28.78,96.82 28.25,96.82 28.12,96.96 28.12,97.26 28.19,97.33 29.03,97.33 29.22,97.52 29.22,97.71 29.03,97.89 28.73,97.89 28.63,97.99 28.63,98.25 28.73,98.35 29.59,98.35 v1(29.97,98.73)
  BOTTOM w0.121: R134.1 31.88,100.18 30.4,100.18 29.97,99.75 v1(29.97,98.73)
MII1_TXD0: length 28
  TOP w0.121: v1(25.53,99.73) 25.73,99.53 U14.22 ; v1(29.84,93.07) 30.32,92.59 33.4,92.59 33.55,92.73 33.55,93.34 33.66,93.45 37.74,93.45 37.83,93.53 37.83,94.51 37.93,94.61 38.59,94.61 38.86,94.34 40.72,94.34 U5.K17
  LYR4 w0.133: v1(25.53,99.73) 26.1,99.16 26.64,99.16 26.78,99.02 26.78,98.79 26.67,98.68 26.24,98.68 26.14,98.58 26.14,98.22 26.21,98.15 27.66,98.15 28,97.8 28,97.55 27.91,97.46 27.34,97.46 27.2,97.33 27.2,97 27.33,96.88 28.57,96.88 28.73,96.72 28.73,96.24 28.57,96.09 28.12,96.09 28.02,95.99 28.02,95.55 28.09,95.48 28.6,95.48 28.73,95.35 28.73,93.93 29.08,93.57 29.34,93.57 v1(29.84,93.07)
MII1_TXD1: length 28
  TOP w0.121: v1(41.52,95.14) U5.K16 ; U14.23 25.23,99.4 v1(24.89,99.73)
  LYR3 w0.133: v1(24.89,99.73) 25.46,99.16 27.18,99.16 27.34,99 27.34,98.81 27.18,98.65 25.53,98.65 25.4,98.52 25.4,98.34 25.5,98.23 28.21,98.23 28.5,98.53 28.5,98.98 28.8,99.29 31.24,99.29 31.75,98.78 31.75,96.24 32.47,95.52 33.32,95.52 33.55,95.75 33.55,96.09 34.09,96.62 39.01,96.62 40.5,95.14 v1(41.52,95.14)
MII1_TXD2: length 28.1
  TOP w0.121: v1(29.84,100.69) 29.59,100.43 24.96,100.43 24.49,99.97 24.49,99.5 24.73,99.26 U14.24 ; U5.K15 v1(43.12,95.14)
  LYR3 w0.121: 41.27,95.54 42.72,95.54 43.12,95.14 v1(43.12,95.14)
  LYR3 w0.133: v1(29.84,100.69) 29.84,101.7 29.97,101.83 31.88,101.83 32,101.7 32,96.5 32.11,96.4 33.43,96.4 33.91,96.88 39.14,96.88 40.48,95.54 41.27,95.54
MII1_TXD3: length 28.3
  TOP w0.121: v1(38.23,94.21) 38.23,94.18 38.47,93.94 U5.J18 ; U14.25 23.69,97.99 23.49,98.18 23.49,99.16 23.77,99.44 23.77,99.95 24.64,100.81 26.11,100.81 26.75,101.45 30.53,101.45 31.11,100.86 31.11,99.79 31.24,99.67 31.52,99.67 31.65,99.8 31.65,100.99 31.75,101.09 32.03,101.09 32.13,100.99 32.13,99.72 32.19,99.66 32.6,99.66 32.69,99.75 32.69,100.05 32.82,100.18 35.18,100.18 v1(36.96,98.4)
  LYR4 w0.133: v1(38.23,94.21) 37.72,94.72 37.72,97.64 v1(36.96,98.4)
MII1_TXEN: length 28.5
  TOP w0.121: v1(41.52,93.54) U5.J16 ; v1(26.23,99.73) U14.21
  LYR3 w0.133: v1(29.84,94.02) 29.82,93.99 29.82,93.61 29.95,93.47 30.86,93.47 31.06,93.68 31.42,93.68 31.55,93.55 31.55,92.13 31.64,92.03 31.86,92.03 32.03,92.2 32.03,93.34 32.16,93.47 32.41,93.47 32.59,93.29 32.59,92.69 32.72,92.56 33.43,92.56 33.66,92.79 33.66,93.68 33.81,93.83 34.01,93.83 34.14,93.7 34.14,93.47 34.29,93.32 37.64,93.32 37.8,93.47 37.8,94.39 38.05,94.64 38.4,94.64 38.73,94.31 38.73,93.64 39.05,93.32 39.38,93.32 39.39,93.33 41.29,93.33 41.3,93.32 v1(41.52,93.54)
  LYR4 w0.133: v1(29.84,94.02) 29.4,94.02 29.16,94.26 29.16,97.08 26.5,99.73 v1(26.23,99.73)
MMC0_CD: length 80.4
  TOP w0.121: v1(42.32,88.73) U5.C15
  LYR3 w0.133: v1(36.55,83.79) 36.73,83.97 47.83,83.97 48.79,84.94 53.11,84.94 53.8,84.25 54.61,84.25 55.91,82.96 55.91,81.13 56.62,80.42 68.12,80.42 72.47,84.76 72.47,99.75 71.5,100.71 v1(71.5,107.92)
  BOTTOM w0.121: v1(42.32,88.73) 41.92,88.33 41.92,86.97 40.93,85.98 37.49,85.98 36.82,85.31 36.82,84.44 36.55,84.17 v1(36.55,83.79) 36.07,83.79 36,83.86 P2.19 ; P10.10 71.38,108.82 71.32,108.76 71.25,108.76 70.87,108.37 R157.1 71.12,108.31 v1(71.5,107.92)
MMC0_CLKO: length 81.6
  TOP w0.121: v1(33.15,85.45) 34.24,86.54 34.24,88.76 36.64,91.16 38.48,91.16 40.06,92.74 40.72,92.74 U5.G17
  LYR3 w0.133: v1(33.15,85.45) 33.14,85.44 33.14,84.42 35.38,82.18 39.95,82.18 40.67,82.91 43.88,82.91 46.39,80.39 47.45,80.39 48.87,78.97 48.87,77.04 49.66,76.24 54.2,76.24 57.23,79.27 69.48,79.27 74.02,83.81 74.02,88.03 79.08,93.09 81.18,93.09 v1(81.64,92.63)
  BOTTOM w0.121: P10.5 85.09,95.23 84.61,94.74 83.97,94.74 R152.2 82.07,93.07 v1(81.64,92.63)
MMC0_CMD: length 92.7
  TOP w0.121: U5.G18 40.04,92.34 38.61,90.91 36.74,90.91 34.54,88.71 34.54,86.21 v1(33.78,85.45) ; v1(83.57,108.81) 82.8,108.05 R151.2
  LYR3 w0.133: v1(83.57,108.81) 83.57,108.69 83.06,108.18 83.06,103.6 73.56,94.1 73.56,83.68 69.45,79.57 57.09,79.57 54,76.48 49.76,76.48 49.15,77.09 49.15,79.58 46.53,82.19 45.64,82.19 44.7,83.14 40.57,83.14 39.95,82.52 39.95,82.52 39.85,82.42 35.47,82.42 33.38,84.52 33.38,85.04 v1(33.78,85.45)
  BOTTOM w0.121: v1(83.57,108.81) 84.39,109.64 P10.3
MMC0_DAT0: length 69.6
  TOP w0.121: v1(41.52,91.94) U5.G16
  LYR3 w0.133: v1(41.1,81.89) 41.53,81.89 41.68,82.04 44.07,82.04 46.39,79.73 47.31,79.73 48.26,78.78 48.26,76.98 49.47,75.77 54.54,75.77 57.51,78.74 69.61,78.74 74.68,83.8 74.68,87.77 78.83,91.92 79.63,91.92 v1(80.39,92.68)
  LYR4 w0.133: v1(41.52,91.94) 41.32,91.94 39.22,89.84 39.22,86.72 39.67,86.26 39.67,83.24 41.02,81.89 v1(41.1,81.89)
  BOTTOM w0.121: v1(80.39,92.68) 80.65,92.68 R153.2 81.92,93.95 82.42,93.95 83.69,95.22 P10.7
MMC0_DAT1: length 68.5
  TOP w0.121: v1(42.32,91.94) U5.G15
  LYR3 w0.133: v1(79.12,92.56) 74.4,87.83 74.4,83.86 69.53,78.99 57.38,78.99 54.39,76.01 49.56,76.01 48.51,77.06 48.51,78.86 47.33,80.05 46.4,80.05 43.95,82.5 v1(41.1,82.5)
  LYR4 w0.121: v1(41.1,82.5) 39.98,83.62 39.98,86.5 ; 39.51,86.97 39.47,87 39.47,87.22 ; v1(42.32,91.94) 41.92,91.54 41.35,91.54 41.13,91.32
  LYR4 w0.133: 39.47,87.22 39.47,89.66 41.13,91.32 ; 39.98,86.5 39.51,86.97
  BOTTOM w0.121: P10.8 82.99,95.16 82.17,94.34 81.03,94.34 R154.2 79.63,93.07 v1(79.12,92.56)
MMC0_DAT2: length 87.2
  TOP w0.121: R150.2 81.03,107.92 v1(81.92,108.81) ; U5.F18 39.62,91.54 38.74,90.66 36.84,90.66 34.82,88.64 34.82,84.96 34.54,84.68 v1(34.42,84.68)
  LYR3 w0.133: v1(81.92,108.81) 81.92,108.69 82.19,108.41 82.19,103.45 72.92,94.18 72.92,84.79 68.25,80.11 56.44,80.11 55.63,80.92 55.63,82.83 54.51,83.95 53.64,83.95 53.04,84.56 48.84,84.56 47.37,83.08 45.54,83.08 44.96,83.67 37.21,83.67 36.68,83.13 35.97,83.13 v1(34.42,84.68)
  BOTTOM w0.121: v1(81.92,108.81) 82.42,109.32 82.55,109.32 82.99,109.76 P10.1
MMC0_DAT3: length 90.6
  TOP w0.121: U5.F17 40.71,91.13 39.58,91.13 38.86,90.41 36.94,90.41 35.18,88.65 35.18,84.68 34.67,84.18 34.29,84.18 v1(33.78,84.68) ; v1(82.68,108.81) 81.92,108.05 R155.2
  LYR3 w0.133: v1(82.68,108.81) 82.68,103.56 73.25,94.13 73.25,84.78 68.28,79.81 56.34,79.81 55.37,80.77 55.37,82.58 54.91,83.03 54.1,83.03 52.83,84.3 49.15,84.3 47.32,82.47 45.75,82.47 44.84,83.38 40.47,83.38 39.85,82.75 35.71,82.75 v1(33.78,84.68)
  BOTTOM w0.121: P10.2 83.69,109.7 82.8,108.81 v1(82.68,108.81)
MMC1_CLK: length 41.5
  TOP w0.121: U5.U9 47.92,100.74 47.92,101.1 47.92,101.11 47.92,101.3 48.07,101.45 48.07,109.51 47.24,110.34 47.24,114.53 P8.21
  TOP w0.203: U13.M6 29.18,107.6 29.47,107.6 v1(29.49,107.62)
  LYR4 w0.133: v1(29.49,107.62) 29.66,107.62 30.83,106.45 35.89,106.45 38.3,108.86 38.3,109.78 41.4,112.88 45.28,112.88 46.48,114.08 P8.21
  BOTTOM w0.121: R110.2 P8.21
MMC1_CMD: length 43.6
  TOP w0.121: P8.20 45.21,116.56 45.21,114.66 46.99,112.88 46.99,110.08 47.82,109.25 47.82,101.64 47.52,101.34 U5.V9
  TOP w0.203: U13.M5 29.03,108.25 29.42,108.25 v1(29.49,108.18)
  LYR4 w0.133: v1(43.94,113.39) 41.4,113.39 38.05,110.03 38.05,108.97 35.79,106.71 31.07,106.71 29.6,108.18 v1(29.49,108.18)
  BOTTOM w0.121: P8.20 42.8,116.69 42.8,114.53 v1(43.94,113.39) R109.2
MMC1_DAT0: length 35.5
  TOP w0.121: v1(39.5,110.08) 38.51,111.07 36.6,111.07 34.81,109.29 U13.A3 ; v1(50.29,113.39) 49.78,112.88 49.78,110.59 49.15,109.96 49.15,104.37 49.16,104.36 49.16,104.27 49.66,103.76 49.66,101.7 49.52,101.56 49.52,100.74 U5.U7
  LYR4 w0.133: v1(39.5,110.08) 40.89,110.08 42.67,111.86 48.77,111.86 v1(50.29,113.39)
  BOTTOM w0.121: R101.2 v1(50.29,113.39) 50.29,114.02 P8.25
MMC1_DAT1: length 39.5
  TOP w0.121: U13.A4 35.05,108.79 35.95,109.68 38.32,109.68 38.43,109.58 39.75,109.58 40.13,109.96 v1(40.13,110.85) ; P8.24 50.16,116.69 50.16,114.53 49.53,113.89 49.53,110.72 48.89,110.08 48.89,104.11 49.4,103.61 49.4,101.83 49.12,101.54 U5.V7
  LYR4 w0.133: v1(47.75,113.39) 46.74,112.37 41.66,112.37 v1(40.13,110.85)
  BOTTOM w0.121: P8.24 47.75,116.56 v1(47.75,113.39) R102.2
MMC1_DAT2: length 41.4
  TOP w0.121: v1(36.96,109.22) 36.27,109.22 36.02,108.97 36.02,108.56 35.74,108.29 U13.A5 ; v1(48.72,99.14) U5.R8
  LYR3 w0.121: v1(48.72,99.14) 48.32,99.54 48.32,100.18
  LYR3 w0.133: v1(36.96,109.22) 38.33,110.59 39.62,110.59 39.88,110.34 44.07,110.34 45.59,108.81 45.59,106.96 47.62,104.93 47.62,100.94 48.32,100.25 48.32,100.18
  LYR4 w0.133: v1(36.96,109.22) 36.96,108.46 35.69,107.19 34.69,107.19 30.53,111.35 29.08,111.35 27.43,113 v1(27.43,113.39)
  BOTTOM w0.121: R103.2 v1(27.43,113.39) 27.43,114.02 P8.5
MMC1_DAT3: length 38.9
  TOP w0.076: U13.B2 33.99,109.8 34.24,110.05 34.24,110.49 34.32,110.57 34.59,110.85
  TOP w0.121: 34.59,110.85 35.31,111.56 v1(35.31,111.65) ; v1(48.72,99.94) U5.T8
  LYR3 w0.133: v1(48.72,99.94) 48.72,100.36 47.89,101.19 47.89,105.05 45.85,107.09 45.85,109.07 44.45,110.46 44.45,111.1 44.17,111.38 35.58,111.38 v1(35.31,111.65)
  LYR4 w0.133: v1(35.31,111.65) 32.63,111.65 31.78,112.5 29.59,112.5 v1(28.7,113.39)
  BOTTOM w0.121: R104.2 v1(28.7,113.39) 27.43,114.66 27.43,116.56 P8.6
MMC1_DAT4: length 38.1
  TOP w0.076: 34.89,109.72 34.71,109.54 34.59,109.54 34.26,109.54 34,109.29 U13.B3
  TOP w0.121: 34.89,109.72 35.99,110.82 v1(35.99,111.79) ; U5.U8 48.72,100.74 48.72,101.52 49.15,101.96 49.15,103.48 48.64,103.99 48.64,109.83 48.51,109.96 48.51,113.51 49.02,114.02 P8.23
  LYR4 w0.133: P8.23 48.01,116.31 40.64,116.31 40.13,115.8 40.13,114.53 37.39,111.79 v1(35.99,111.79)
  BOTTOM w0.121: R105.2 P8.23
MMC1_DAT5: length 36.7
  TOP w0.076: 34.79,109.04 34.26,109.04 34.01,108.79 U13.B4
  TOP w0.121: 34.79,109.04 34.92,109.04 34.92,109.04 34.93,109.04 36.5,110.62 36.88,110.62 v1(36.91,110.64) ; U5.V8 48.32,109.77 48.26,109.83 48.26,114.27 47.75,114.78 47.75,116.56 P8.22
  LYR4 w0.133: v1(36.91,110.64) 36.93,110.62 38.13,110.62 41.3,113.79 44.81,113.79 v1(45.21,113.39)
  BOTTOM w0.121: P8.22 45.21,116.56 v1(45.21,113.39) R106.2
MMC1_DAT6: length 40.4
  TOP w0.076: U13.B5 34,108.29 34.25,108.53 34.87,108.53
  TOP w0.121: v1(35.56,108.71) 35.54,108.73 35.37,108.73 35.18,108.53 35.05,108.53 34.87,108.53 ; v1(47.92,99.14) U5.R9
  LYR3 w0.133: v1(35.56,108.71) 36.02,108.25 38.68,108.25 39.88,109.45 44.07,109.45 45.09,108.43 45.09,106.7 46.1,105.69 46.1,100.95 v1(47.92,99.14)
  LYR4 w0.133: v1(24.89,113.39) 25.65,114.15 27.94,114.15 28.3,113.79 28.3,113.16 29.34,112.12 30.48,112.12 34.06,108.54 35.18,108.54 35.36,108.72 35.55,108.72 v1(35.56,108.71)
  BOTTOM w0.121: P8.3 24.89,114.02 v1(24.89,113.39) R107.2
MMC1_DAT7: length 42.9
  TOP w0.076: 34.82,108.03 34.8,108.04 34.25,108.04 U13.B6
  TOP w0.121: 34.82,108.03 35.89,108.03 36.42,108.56 v1(36.42,108.76) ; v1(47.92,99.94) U5.T9
  LYR3 w0.133: v1(36.42,108.76) 36.5,108.69 38.73,108.69 40,109.96 44.07,109.96 45.34,108.69 45.34,106.78 46.48,105.64 46.48,101.37 v1(47.92,99.94)
  LYR4 w0.133: v1(26.16,113.39) 26.57,113.79 27.66,113.79 27.94,113.51 27.94,113 29.21,111.73 30.48,111.73 34.04,108.18 35.84,108.18 v1(36.42,108.76)
  BOTTOM w0.121: R108.2 v1(26.16,113.39) 24.89,114.66 24.89,116.56 P8.4
MODE2: length 3.9
  TOP w0.121: U14.15 29.51,97.49 v1(29.84,97.83)
  BOTTOM w0.121: R138.2 R113.1 31.01,98.78 30.46,98.23 30.44,98.23 30.21,97.99 30.21,97.97 30.06,97.83 v1(29.84,97.83)
OSC1_IN: length 8.2
  TOP w0.121: U5.A6 51.05,86.4 51.05,85.7 50.93,85.57 50.93,84.18 51.56,83.54 v1(51.56,82.91) 51.56,82.08 51.33,81.84 Y1.1
  BOTTOM w0.121: C21.2 51.88,82.59 v1(51.56,82.91)
OSC1_OUT: length 8.6
  TOP w0.121: U5.A4 51.52,87.01 51.75,86.78 51.75,85.51 51.56,85.32 51.56,84.43 52.45,83.54 52.83,83.54 v1(53.47,82.91) 53.47,82.08 53.7,81.84 Y1.4
  BOTTOM w0.121: C22.2 53.15,82.59 v1(53.47,82.91)
P_BYPASS: length 2.6
  TOP w0.203: v1(21.62,84.28) 21.65,84.24 22.22,84.24 22.46,84.01 U2.47
  BOTTOM w0.381: v1(21.62,84.28) 21.59,84.25 C4.2
P_INT_LDO: length 3.1
  TOP w0.121: C3.2 21.78,85.45 21.11,84.77 21.11,84.05 21.36,83.79 21.97,83.79 22.06,83.71 U2.48
P_L1: length 1
  TOP w0.203: U2.20 24.86,76.3
  vias: v1(23.75,75.03) v1(24.38,75.03)
P_L2: length 0.6
  TOP w0.203: 26.06,76.66 U2.23
  vias: v1(26.04,75.03) v1(26.67,75.03)
P_L3: length 2.9
  BOTTOM w0.381: 30.61,81.83 L3.1 29.97,81.83 v1(29.97,82.52) v1(30.61,82.52) 30.61,81.83
PHY_VDDCR: length 4.1
  TOP w0.254: U14.6 27.23,93.19 27.61,92.81 v1(27.62,92.81)
  BOTTOM w0.381: C136.1 C134.1 28.57,93.06 28.33,92.81 v1(27.62,92.81)
PHY_XTAL1: length 6.5
  TOP w0.152: Y3.1 28.38,90.13 28.09,89.84 26.84,89.84 v1(26.82,89.86)
  BOTTOM w0.121: R142.1 27.3,91.16 R141.2 C143.1 28.45,90.14 28.17,89.87 26.83,89.87 v1(26.82,89.86)
PHY_XTAL2: length 3.5
  TOP w0.121: U14.4 26.23,93.06 26.29,93 26.29,92.31 v1(26.29,92.3)
  BOTTOM w0.121: v1(26.29,92.3) 26.42,92.18 R143.1 26.42,90.53 R141.1
PHYX: length 3.8
  TOP w0.121: v1(25.91,91.03) 25.72,90.84 Y3.2
  BOTTOM w0.121: v1(25.91,91.03) 25.27,90.4 C142.1 25.15,91.16 25.4,91.41 R143.2
PMIC_INT: length 23.8
  TOP w0.121: R1.2 23.75,85.45 23.05,84.75 v1(22.99,84.75) 23.26,84.48 U2.45 ; v1(38.35,84.81) 38.35,85.52 38.99,86.16 38.99,87.01 U5.B18
  LYR3 w0.133: v1(22.99,84.75) 23.43,85.19 31.11,85.19 31.88,85.95 34.54,85.95 36.2,84.3 37.85,84.3 v1(38.35,84.81)
PMIC_PGOOD: length 32.9
  TOP w0.121: v1(28.32,77.89) 27.95,78.26 27.95,78.36 27.75,78.57 U2.26 ; v1(42.32,87.93) U5.B15 ; v1(31.71,75.71) 31.75,75.74 32.72,75.74 33.15,75.31 U16.2
  LYR3 w0.121: 41.34,88.33 41.92,88.33 v1(42.32,87.93)
  LYR3 w0.133: v1(31.71,75.71) 31.7,75.71 31.68,75.69 31.09,75.69 28.9,77.89 v1(28.32,77.89) ; v1(30.73,88.37) 30.99,88.11 31.75,88.11 32.77,89.13 34.22,89.13 34.25,89.1 34.59,89.1 34.61,89.13 36.96,89.13 37.59,88.49 37.59,88.37 38.1,87.86 40.26,87.86 40.73,88.33 41.34,88.33
  LYR4 w0.133: v1(30.73,88.37) 29.46,87.1 29.46,79.03 v1(28.32,77.89)
PMIC_POWR_EN: length 65.4
  TOP w0.121: v1(50.32,88.73) U5.C6 ; v1(19.68,79.37) U2.9
  LYR3 w0.133: v1(59.92,75.87) 57.84,73.79 47.83,73.79 47.14,74.47 43.23,74.47 42.86,74.1 36.11,74.1 35.58,73.58 31.07,73.58 30.51,74.14 24,74.14 21.46,76.68 21.46,77.59 v1(19.68,79.37)
  LYR4 w0.133: v1(50.32,88.73) 50.32,87.58 51.82,86.08 54.61,86.08 56.13,84.56 56.39,84.56 59.31,81.64 59.31,76.43 59.87,75.87 v1(59.92,75.87)
PROC_A15: length 14
  TOP w0.121: v1(41.12,79.73) 40.94,79.73 39.74,80.94 39.74,85.59 40.74,86.59 41.77,86.59 42.32,87.13 U5.A15
  BOTTOM w0.121: R18.1 42.48,77.7 42.6,77.82 42.6,79.12 41.99,79.73 v1(41.12,79.73)
PWR_BUT: length 56.3
  TOP w0.121: v1(28.32,77.19) 27.81,77.19 27.33,77.67 U2.25 ; S3.2 S3.4 14.91,104.85 18.81,100.95 v1(22.3,100.95)
  LYR4 w0.133: v1(22.3,100.95) 24.64,98.62 24.64,96.48 28.79,92.33 28.79,87.82 27.91,86.94 27.91,77.6 v1(28.32,77.19) 30.28,75.23 30.28,68 P9.9
PWR_LEDR: length 2.3
  TOP w0.381: v1(3.81,84.56) 4.25,85 D1.1
  BOTTOM w0.381: R12.2 3.94,84.43 v1(3.81,84.56)
RBIAS: length 2.7
  TOP w0.121: U14.32 23.46,94.49 23.3,94.34 23.3,94.02 v1(22.67,93.38)
  BOTTOM w0.121: v1(22.67,93.38) R144.1
RCLKIN: length 8
  TOP w0.121: v1(26.73,92.81) 26.73,93.07 26.73,93.07 U14.5
  BOTTOM w0.121: v1(26.73,92.81) 27.37,92.18 C161.1 27.96,91.65 28.26,91.65 28.45,91.47 R142.2 28.45,91.08 28.62,90.91 29.04,90.91 29.21,91.08 29.21,91.72 29.34,91.85 29.64,91.85 29.74,91.74 29.74,91.28 29.97,91.06 31.27,91.06 R140.2
REFCLKO: length 8
  TOP w0.121: U14.7 27.73,93.38 28.04,93.07 29.21,93.07 29.97,92.3 29.97,91.54 C162.2 R118.1 R124.2 30.67,92.05 v1(30.61,92.11)
  BOTTOM w0.121: R131.2 v1(30.61,92.11)
RXD0/MODE0: length 4.1
  TOP w0.121: U14.11 29.98,95.49 30.42,95.92 v1(30.61,95.92) 30.61,95.61 30.73,95.48 31.24,95.48 31.37,95.61 R128.2
  BOTTOM w0.121: R128.2 v1(30.61,95.92)
RXD1/MODE1: length 4
  TOP w0.121: R127.2 31.37,94.59 31.27,94.49 30.73,94.49 30.61,94.62 v1(30.61,94.97) 30.59,94.99 30.29,94.99 U14.10
  BOTTOM w0.121: R127.2 v1(30.61,94.97)
RXD2/RMIISEL: length 4.1
  TOP w0.121: U14.9 30.14,94.49 v1(30.61,94.02) 30.61,93.7 30.73,93.57 31.24,93.57 31.37,93.7 R126.2
  BOTTOM w0.121: R126.2 v1(30.61,94.02)
RXD3/PHYAD2: length 4.3
  TOP w0.121: U14.8 28.23,93.59 28.36,93.47 30.21,93.47 v1(30.61,93.07) R125.2
  BOTTOM w0.121: R125.2 v1(30.61,93.07)
RXDV: length 2.7
  TOP w0.121: R129.2 23.01,99.14 23.11,99.03 23.11,97.96 23.58,97.49 U14.26
RXER/PHYAD0: length 4.1
  TOP w0.121: R133.2 31.37,96.49 31.27,96.4 30.73,96.4 30.61,96.53 v1(30.61,96.88) 30.22,96.49 U14.13
  BOTTOM w0.121: R133.2 v1(30.61,96.88)
RXN: length 18.4
  TOP w0.095: U14.30 23.43,95.49 23.29,95.35 22.73,95.35 v1(22.67,95.29) 22.33,94.95 22.05,94.95 21.49,95.52 21.49,97.12 20.69,97.92 19.82,97.92 19.04,97.13 18.03,97.13 17.4,97.76 17.4,99.04 17.65,99.3 18.29,99.3 18.54,99.04 P5.2
  BOTTOM w0.095: R121.1 v1(22.67,95.29)
  BOTTOM w0.121: C138.1 P5.2
RXP: length 15.9
  TOP w0.095: U14.31 23.41,94.99 23.33,95.07 23.08,95.07 22.92,94.92 22.92,94.59 v1(22.67,94.34) 22.33,94.67 21.94,94.67 21.21,95.4 21.21,97 20.57,97.64 19.94,97.64 19.15,96.85 17.92,96.85 17.12,97.65 17.12,99.16 16.87,99.42 P5.1
  BOTTOM w0.095: R120.1 v1(22.67,94.34)
  BOTTOM w0.121: C137.1 P5.1
SPI1_CS0: length 24.7
  TOP w0.121: v1(44.72,88.73) U5.C12
  LYR4 w0.133: v1(44.72,88.73) 44.72,86.98 45.31,86.39 45.31,80.98 46.43,79.86 47.34,79.86 48.39,78.82 48.39,76.05 50.57,73.86 50.57,72.09 51.08,71.58 52.1,71.58 P9.28
SPI1_D0: length 29.4
  TOP w0.121: U5.B13 v1(43.92,87.93)
  LYR4 w0.133: v1(43.92,87.93) 43.51,87.53 43.51,86.92 44.06,86.37 44.06,82.77 44.6,82.22 44.6,80.79 46.05,79.34 46.05,78.26 46.89,77.42 46.89,76.5 50.05,73.34 50.05,70.65 50.42,70.28 50.42,69.36 51.35,68.43 53.21,68.43 53.47,68.17 55.5,68.17 56.64,67.03
SPI1_D1: length 27.1
  TOP w0.121: v1(44.72,89.54) U5.D12
  LYR4 w0.121: v1(44.72,89.54) 45.12,89.14 45.12,88.24
  LYR4 w0.133: 56.64,69.57 55.93,69.57 52.83,72.66 52.83,73.16 52.08,73.91 50.9,73.91 48.69,76.12 48.69,78.87 47.37,80.19 46.43,80.19 45.55,81.07 45.55,86.58 45.12,87.01 45.12,88.24
SPI1_SCLK: length 30
  TOP w0.121: U5.A13 v1(43.92,87.13)
  LYR4 w0.133: v1(43.92,87.13) 44.35,86.7 44.35,82.93 44.86,82.42 44.86,80.95 46.18,79.63 46.71,79.63 46.86,79.48 46.86,78.03 47.35,77.55 47.35,76.63 50.32,73.66 50.32,71.51 51.27,70.56 51.92,70.56 53.09,69.4 53.09,69.24 53.89,68.43 57.78,68.43 P9.31
SYS_5V: length 67.6
  TOP w0.203: U2.8 20.35,79.77 v1(20.19,79.92) 20.44,80.17 U2.7 ; U2.2 20.55,82.17 v1(20.19,82.52) ; v1(28.32,81.57) 28.32,81.32 27.97,80.97 U2.32 ; U2.39 v1(25.66,84.24) ; U2.22 25.66,76.43 v1(25.53,76.3) 25.26,76.57 U2.21 ; U2.42 24.46,84.13 v1(24.38,84.24)
  TOP w0.381: v1(16.13,109.83) 15.75,110.21 13.84,110.21 13.72,110.08 13.72,112.75
  LYR4 w0.381: v1(16.13,109.83) 16.18,109.78 16.18,109.04 21.29,103.94 22.17,103.94 v2(22.43,103.68) 21.77,103.03 21.77,100.63 23.37,99.03 23.37,92.43 22.77,91.84 22.77,89.67 23.98,88.47 24.92,88.47 26.31,87.08 26.31,84.89 v1(25.66,84.24)
  LYR4 w0.762: v1(25.53,76.3) 25.18,75.95 25.18,73.6 28.7,70.08 P9.8
  BOTTOM w0.381: U4.2 20.83,105.61 21.72,104.72 C17.1 21.97,104.24 22.35,103.86 22.35,103.76 v2(22.43,103.68) ; v1(25.66,84.24) 25.66,83.61 C13.2 24.89,83.48 24.89,83.99 24.64,84.24 v1(24.38,84.24) ; C10.2 20.38,79.73 v1(20.19,79.92) ; v1(25.53,76.3) 25.21,76.62 C7.2 C8.2
  BOTTOM w0.762: P9.7 P9.8
  vias: v1(7.37,72.87) v1(8,74.02) v1(8.13,72.87) v1(14.68,78.54) v1(17.81,79.8) v1(18.47,80.62)
SYS_RESETN: length 97
  TOP w0.121: U16.4 32.5,70.83 P9.10 ; U5.A10 46.72,87.2 46.1,86.59 46.1,85.95 45.21,85.06 44.32,85.06 43.05,83.79 43.05,81.89 43.31,81.64 v1(43.81,81.64) ; S1.2 S1.4 13.69,114.25 v1(13.72,114.27) ; U14.19 v1(27.23,99.73)
  LYR3 w0.133: v1(43.81,81.64) 43.31,81.13 39.75,81.13 39.5,80.87 36.13,80.87 v1(35.69,81.32)
  LYR4 w0.133: v1(13.72,114.27) 15.11,112.88 21.97,112.88 26.03,108.82 26.03,100.93 v1(27.23,99.73) 29.78,99.73 31.67,97.84 31.67,84.23 v1(31.37,83.92) 31.88,83.41 31.88,80.87 29.02,78.02 v1(29.02,77.19) 30.71,75.5 30.71,70.1 P9.10
  BOTTOM w0.121: C30.1 C24.1 R14.2 v1(29.02,77.19) ; v1(35.69,81.32) P2.15 32.19,81.32 31.88,81.64 31.88,83.41 v1(31.37,83.92)
TCT_RCT: length 6.4
  BOTTOM w0.121: C141.1 R137.1 P5.5 17.27,94.34 P5.4
TESTOUT: length 2.9
  TOP w0.121: U5.A3 52.83,87.02 TP3.1
TIMER4: length 33.6
  TOP w0.121: v1(49.52,99.14) U5.R7
  LYR3 w0.121: 49.12,100.18 49.12,99.54 v1(49.52,99.14)
  LYR3 w0.133: v1(35.43,113.39) 36.73,112.09 43.84,112.09 44.7,111.23 44.7,110.72 45.59,109.83 45.94,109.83 47.12,108.65 47.12,106.27 48.15,105.24 48.15,101.43 49.12,100.46 49.12,100.18
  LYR4 w0.133: P8.7 28.7,114.27 30.1,112.88 34.92,112.88 v1(35.43,113.39)
TIMER5: length 30.6
  TOP w0.121: v1(50.32,99.94) U5.T6
  LYR3 w0.133: v1(37.21,113.39) 37.72,112.88 45.15,112.88 47.62,110.4 47.62,106.65 49.78,104.5 49.78,100.81 50.32,100.28 v1(50.32,99.94)
  LYR4 w0.133: P8.9 32.26,114.27 36.32,114.27 v1(37.21,113.39)
